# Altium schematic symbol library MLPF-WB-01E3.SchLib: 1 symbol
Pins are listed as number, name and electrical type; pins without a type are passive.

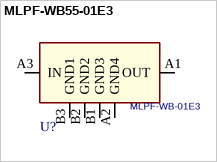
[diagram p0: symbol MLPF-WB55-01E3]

## MLPF-WB55-01E3
designator U?, comment MLPF-WB-01E3
footprint ST_CSP6_50x58P2x3_160x100x4
pins: A1 OUT, A2 GND4, A3 IN, B1 GND3, B2 GND2, B3 GND1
